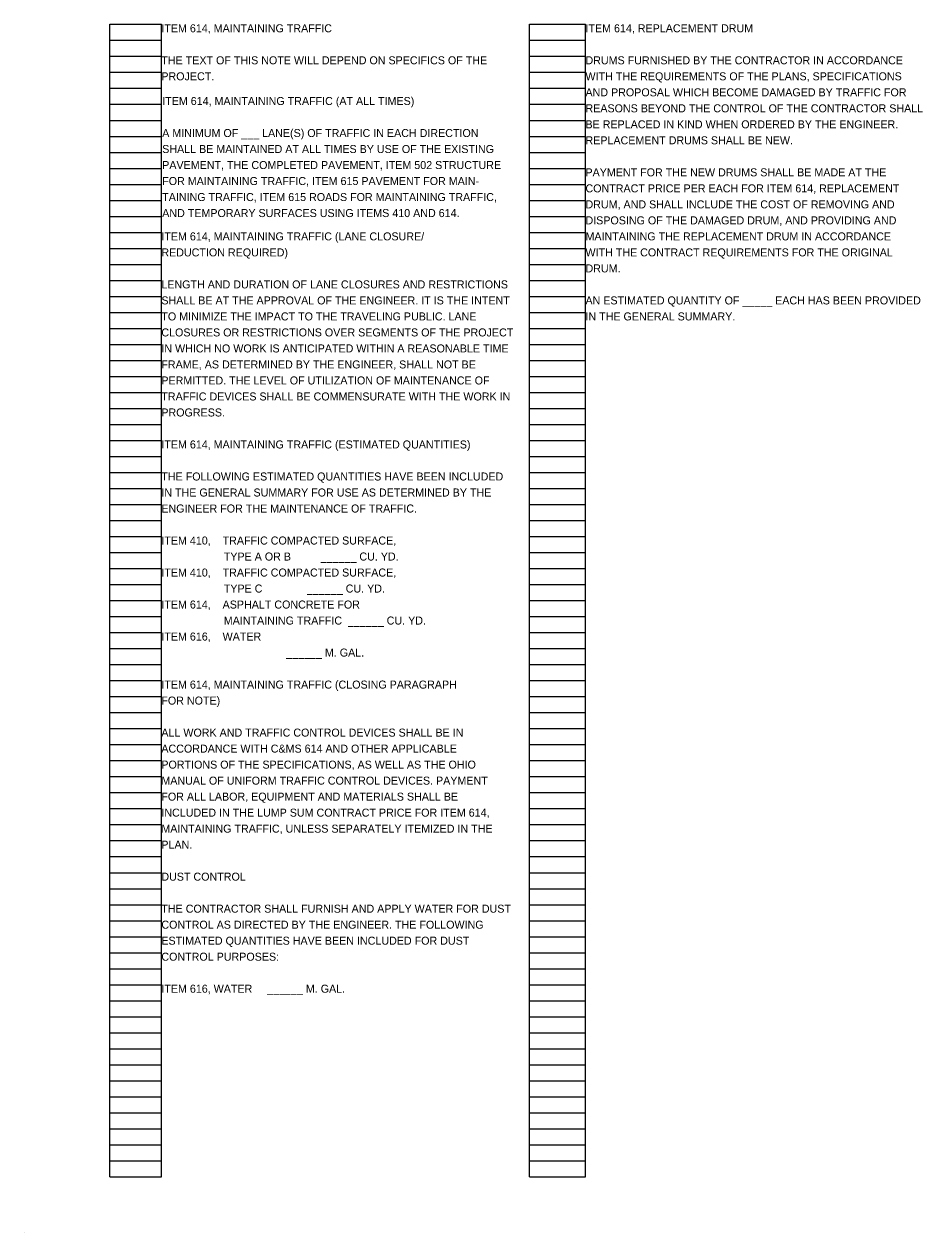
# Model space of a CAD drawing. Extents: x -36 to 68, y -39 to 86.
# Drawn here: x 0 to 15.72, y -24 to -2.86 of the extents above; entities that cross this region are included whole.
import ezdxf

# ---------------------------------------------------------------- set-up
doc = ezdxf.new("R2010")
doc.units = 0
doc.layers.add('SH_Data', color=7, linetype='Continuous')
doc.layers.add('SH_Text', color=7, linetype='Continuous')

msp = doc.modelspace()

# ---------------------------------------------------------------- linework, layer by layer
at = {"layer": 'SH_Data'}
for p, q in [((1.5, -23.02), (1.5, -2.86)), ((1.5, -2.86), (2.4, -2.86)), ((2.4, -23.02), (2.4, -2.86)), ((8.84, -23.02), (8.84, -2.86)), ((8.84, -2.86), (9.82, -2.86)), ((9.82, -23.02), (9.82, -2.86)), ((1.5, -3.14), (2.4, -3.14)), ((8.84, -3.14), (9.82, -3.14)), ((1.5, -3.42), (2.4, -3.42)), ((8.84, -3.42), (9.82, -3.42)), ((1.5, -3.7), (2.4, -3.7)), ((8.84, -3.7), (9.82, -3.7)), ((1.5, -3.98), (2.4, -3.98)), ((8.84, -3.98), (9.82, -3.98)), ((1.5, -4.26), (2.4, -4.26)), ((8.84, -4.26), (9.82, -4.26)), ((1.5, -4.54), (2.4, -4.54)), ((8.84, -4.54), (9.82, -4.54)), ((1.5, -4.82), (2.4, -4.82)), ((8.84, -4.82), (9.82, -4.82)), ((1.5, -5.1), (2.4, -5.1)), ((8.84, -5.1), (9.82, -5.1)), ((1.5, -5.38), (2.4, -5.38)), ((8.84, -5.38), (9.82, -5.38)), ((1.5, -5.66), (2.4, -5.66)), ((8.84, -5.66), (9.82, -5.66)), ((1.5, -5.94), (2.4, -5.94)), ((8.84, -5.94), (9.82, -5.94)), ((1.5, -6.22), (2.4, -6.22)), ((8.84, -6.22), (9.82, -6.22)), ((1.5, -6.5), (2.4, -6.5)), ((8.84, -6.5), (9.82, -6.5)), ((1.5, -6.78), (2.4, -6.78)), ((8.84, -6.78), (9.82, -6.78)), ((1.5, -7.06), (2.4, -7.06)), ((8.84, -7.06), (9.82, -7.06)), ((1.5, -7.34), (2.4, -7.34)), ((8.84, -7.34), (9.82, -7.34)), ((1.5, -7.62), (2.4, -7.62)), ((8.84, -7.62), (9.82, -7.62)), ((1.5, -7.9), (2.4, -7.9)), ((8.84, -7.9), (9.82, -7.9)), ((1.5, -8.18), (2.4, -8.18)), ((8.84, -8.18), (9.82, -8.18)), ((1.5, -8.46), (2.4, -8.46)), ((8.84, -8.46), (9.82, -8.46)), ((1.5, -8.74), (2.4, -8.74)), ((8.84, -8.74), (9.82, -8.74)), ((1.5, -9.02), (2.4, -9.02)), ((8.84, -9.02), (9.82, -9.02)), ((1.5, -9.3), (2.4, -9.3)), ((8.84, -9.3), (9.82, -9.3)), ((1.5, -9.58), (2.4, -9.58)), ((8.84, -9.58), (9.82, -9.58)), ((1.5, -9.86), (2.4, -9.86)), ((8.84, -9.86), (9.82, -9.86)), ((1.5, -10.14), (2.4, -10.14)), ((8.84, -10.14), (9.82, -10.14)), ((1.5, -10.42), (2.4, -10.42)), ((8.84, -10.42), (9.82, -10.42)), ((1.5, -10.7), (2.4, -10.7)), ((8.84, -10.7), (9.82, -10.7)), ((1.5, -10.98), (2.4, -10.98)), ((8.84, -10.98), (9.82, -10.98)), ((1.5, -11.26), (2.4, -11.26)), ((8.84, -11.26), (9.82, -11.26)), ((1.5, -11.54), (2.4, -11.54)), ((8.84, -11.54), (9.82, -11.54)), ((1.5, -11.82), (2.4, -11.82)), ((8.84, -11.82), (9.82, -11.82)), ((1.5, -12.1), (2.4, -12.1)), ((8.84, -12.1), (9.82, -12.1)), ((1.5, -12.38), (2.4, -12.38)), ((8.84, -12.38), (9.82, -12.38)), ((1.5, -12.66), (2.4, -12.66)), ((8.84, -12.66), (9.82, -12.66)), ((1.5, -12.94), (2.4, -12.94)), ((8.84, -12.94), (9.82, -12.94)), ((1.5, -13.22), (2.4, -13.22)), ((8.84, -13.22), (9.82, -13.22)), ((1.5, -13.5), (2.4, -13.5)), ((8.84, -13.5), (9.82, -13.5)), ((1.5, -13.78), (2.4, -13.78)), ((8.84, -13.78), (9.82, -13.78)), ((1.5, -14.06), (2.4, -14.06)), ((8.84, -14.06), (9.82, -14.06)), ((1.5, -14.34), (2.4, -14.34)), ((8.84, -14.34), (9.82, -14.34)), ((1.5, -14.62), (2.4, -14.62)), ((8.84, -14.62), (9.82, -14.62)), ((1.5, -14.9), (2.4, -14.9)), ((8.84, -14.9), (9.82, -14.9)), ((1.5, -15.18), (2.4, -15.18)), ((8.84, -15.18), (9.82, -15.18)), ((1.5, -15.46), (2.4, -15.46)), ((8.84, -15.46), (9.82, -15.46)), ((1.5, -15.74), (2.4, -15.74)), ((8.84, -15.74), (9.82, -15.74)), ((1.5, -16.02), (2.4, -16.02)), ((8.84, -16.02), (9.82, -16.02)), ((1.5, -16.3), (2.4, -16.3)), ((8.84, -16.3), (9.82, -16.3)), ((1.5, -16.58), (2.4, -16.58)), ((8.84, -16.58), (9.82, -16.58)), ((1.5, -16.86), (2.4, -16.86)), ((8.84, -16.86), (9.82, -16.86)), ((1.5, -17.14), (2.4, -17.14)), ((8.84, -17.14), (9.82, -17.14)), ((1.5, -17.42), (2.4, -17.42)), ((8.84, -17.42), (9.82, -17.42)), ((1.5, -17.7), (2.4, -17.7)), ((8.84, -17.7), (9.82, -17.7)), ((1.5, -17.98), (2.4, -17.98)), ((8.84, -17.98), (9.82, -17.98)), ((1.5, -18.26), (2.4, -18.26)), ((8.84, -18.26), (9.82, -18.26)), ((1.5, -18.54), (2.4, -18.54)), ((8.84, -18.54), (9.82, -18.54)), ((1.5, -18.82), (2.4, -18.82)), ((8.84, -18.82), (9.82, -18.82)), ((1.5, -19.1), (2.4, -19.1)), ((8.84, -19.1), (9.82, -19.1)), ((1.5, -19.38), (2.4, -19.38)), ((8.84, -19.38), (9.82, -19.38)), ((1.5, -19.66), (2.4, -19.66)), ((8.84, -19.66), (9.82, -19.66)), ((1.5, -19.94), (2.4, -19.94)), ((8.84, -19.94), (9.82, -19.94)), ((1.5, -20.22), (2.4, -20.22)), ((8.84, -20.22), (9.82, -20.22)), ((1.5, -20.5), (2.4, -20.5)), ((8.84, -20.5), (9.82, -20.5)), ((1.5, -20.78), (2.4, -20.78)), ((8.84, -20.78), (9.82, -20.78)), ((1.5, -21.06), (2.4, -21.06)), ((8.84, -21.06), (9.82, -21.06)), ((1.5, -21.34), (2.4, -21.34)), ((8.84, -21.34), (9.82, -21.34)), ((1.5, -21.62), (2.4, -21.62)), ((8.84, -21.62), (9.82, -21.62)), ((1.5, -21.9), (2.4, -21.9)), ((8.84, -21.9), (9.82, -21.9)), ((1.5, -22.18), (2.4, -22.18)), ((8.84, -22.18), (9.82, -22.18)), ((1.5, -22.46), (2.4, -22.46)), ((8.84, -22.46), (9.82, -22.46)), ((1.5, -22.74), (2.4, -22.74)), ((8.84, -22.74), (9.82, -22.74)), ((1.5, -23.02), (2.4, -23.02)), ((8.84, -23.02), (9.82, -23.02)), ((0, -24), (0, -24))]:
    msp.add_line(p, q, dxfattribs=at)

# ---------------------------------------------------------------- texts
at = {"layer": 'SH_Text'}
for s, p in [('ITEM 614, MAINTAINING TRAFFIC', (2.4, -3)), ('ITEM 614, REPLACEMENT DRUM', (9.82, -3)), ('THE TEXT OF THIS NOTE WILL DEPEND ON SPECIFICS OF THE', (2.4, -3.56)), ('DRUMS FURNISHED BY THE CONTRACTOR IN ACCORDANCE', (9.82, -3.56)), ('PROJECT.', (2.4, -3.84)), ('WITH THE REQUIREMENTS OF THE PLANS, SPECIFICATIONS', (9.82, -3.84)), ('AND PROPOSAL WHICH BECOME DAMAGED BY TRAFFIC FOR', (9.82, -4.12)), ('ITEM 614, MAINTAINING TRAFFIC (AT ALL TIMES)', (2.415, -4.272)), ('REASONS BEYOND THE CONTROL OF THE CONTRACTOR SHALL', (9.82, -4.4)), ('BE REPLACED IN KIND WHEN ORDERED BY THE ENGINEER.', (9.82, -4.68)), ('A MINIMUM OF ___ LANE(S) OF TRAFFIC IN EACH DIRECTION', (2.415, -4.832)), ('REPLACEMENT DRUMS SHALL BE NEW.', (9.82, -4.96)), ('SHALL BE MAINTAINED AT ALL TIMES BY USE OF THE EXISTING', (2.415, -5.112)), ('PAVEMENT, THE COMPLETED PAVEMENT, ITEM 502 STRUCTURE', (2.415, -5.392)), ('PAYMENT FOR THE NEW DRUMS SHALL BE MADE AT THE', (9.82, -5.52)), ('FOR MAINTAINING TRAFFIC, ITEM 615 PAVEMENT FOR MAIN-', (2.415, -5.672)), ('CONTRACT PRICE PER EACH FOR ITEM 614, REPLACEMENT', (9.82, -5.8)), ('TAINING TRAFFIC, ITEM 615 ROADS FOR MAINTAINING TRAFFIC,', (2.415, -5.952)), ('AND TEMPORARY SURFACES USING ITEMS 410 AND 614.', (2.415, -6.232)), ('DRUM, AND SHALL INCLUDE THE COST OF REMOVING AND', (9.82, -6.08)), ('DISPOSING OF THE DAMAGED DRUM, AND PROVIDING AND', (9.82, -6.36)), ('ITEM 614, MAINTAINING TRAFFIC (LANE CLOSURE/', (2.4, -6.64)), ('MAINTAINING THE REPLACEMENT DRUM IN ACCORDANCE', (9.82, -6.64)), ('REDUCTION REQUIRED)', (2.4, -6.92)), ('WITH THE CONTRACT REQUIREMENTS FOR THE ORIGINAL', (9.82, -6.92)), ('DRUM.', (9.82, -7.2)), ('LENGTH AND DURATION OF LANE CLOSURES AND RESTRICTIONS', (2.4, -7.48)), ('SHALL BE AT THE APPROVAL OF THE ENGINEER. IT IS THE INTENT', (2.4, -7.76)), ('AN ESTIMATED QUANTITY OF _____ EACH HAS BEEN PROVIDED', (9.82, -7.76)), ('TO MINIMIZE THE IMPACT TO THE TRAVELING PUBLIC. LANE', (2.4, -8.04)), ('IN THE GENERAL SUMMARY.', (9.82, -8.04)), ('CLOSURES OR RESTRICTIONS OVER SEGMENTS OF THE PROJECT', (2.4, -8.32)), ('IN WHICH NO WORK IS ANTICIPATED WITHIN A REASONABLE TIME', (2.4, -8.6)), ('FRAME, AS DETERMINED BY THE ENGINEER, SHALL NOT BE', (2.4, -8.88)), ('PERMITTED. THE LEVEL OF UTILIZATION OF MAINTENANCE OF', (2.4, -9.16)), ('TRAFFIC DEVICES SHALL BE COMMENSURATE WITH THE WORK IN', (2.4, -9.44)), ('PROGRESS.', (2.4, -9.72)), ('ITEM 614, MAINTAINING TRAFFIC (ESTIMATED QUANTITIES)', (2.4, -10.28)), ('THE FOLLOWING ESTIMATED QUANTITIES HAVE BEEN INCLUDED', (2.4, -10.84)), ('IN THE GENERAL SUMMARY FOR USE AS DETERMINED BY THE', (2.4, -11.12)), ('ENGINEER FOR THE MAINTENANCE OF TRAFFIC.', (2.4, -11.4)), ('ITEM 410,    TRAFFIC COMPACTED SURFACE,', (2.4, -11.96)), ('                     TYPE A OR B          ______ CU. YD.', (2.4, -12.24)), ('ITEM 410,    TRAFFIC COMPACTED SURFACE,', (2.4, -12.52)), ('                     TYPE C               ______ CU. YD.', (2.4, -12.8)), ('ITEM 614,    ASPHALT CONCRETE FOR', (2.4, -13.08)), ('                     MAINTAINING TRAFFIC  ______ CU. YD.', (2.4, -13.36)), ('ITEM 616,    WATER', (2.4, -13.64)), ('                                          ______ M. GAL.', (2.4, -13.92)), ('ITEM 614, MAINTAINING TRAFFIC (CLOSING PARAGRAPH', (2.4, -14.48)), ('FOR NOTE)', (2.4, -14.76)), ('ALL WORK AND TRAFFIC CONTROL DEVICES SHALL BE IN', (2.4, -15.32)), ('ACCORDANCE WITH C&MS 614 AND OTHER APPLICABLE', (2.4, -15.6)), ('PORTIONS OF THE SPECIFICATIONS, AS WELL AS THE OHIO', (2.4, -15.88)), ('MANUAL OF UNIFORM TRAFFIC CONTROL DEVICES. PAYMENT', (2.4, -16.16)), ('FOR ALL LABOR, EQUIPMENT AND MATERIALS SHALL BE', (2.4, -16.44)), ('INCLUDED IN THE LUMP SUM CONTRACT PRICE FOR ITEM 614,', (2.4, -16.72)), ('MAINTAINING TRAFFIC, UNLESS SEPARATELY ITEMIZED IN THE', (2.4, -17)), ('PLAN.', (2.4, -17.28)), ('DUST CONTROL', (2.4, -17.84)), ('THE CONTRACTOR SHALL FURNISH AND APPLY WATER FOR DUST', (2.4, -18.4)), ('CONTROL AS DIRECTED BY THE ENGINEER. THE FOLLOWING', (2.4, -18.68)), ('ESTIMATED QUANTITIES HAVE BEEN INCLUDED FOR DUST', (2.4, -18.96)), ('CONTROL PURPOSES:', (2.4, -19.24)), ('ITEM 616, WATER     ______ M. GAL.', (2.4, -19.8))]:
    msp.add_text(s, height=0.14, dxfattribs=at).set_placement(p)

doc.saveas('drawing.dxf')
